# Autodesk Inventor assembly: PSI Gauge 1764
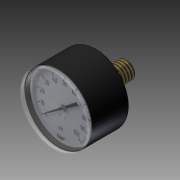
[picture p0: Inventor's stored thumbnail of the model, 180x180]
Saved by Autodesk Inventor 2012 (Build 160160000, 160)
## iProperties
Created: 2010-02
Part Number: PSI Gauge 1764
Document SubType Name: Assembly
Designer: jgehrig
Author: jgehrig
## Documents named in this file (5)
- R:\CAD Archives\Pneumatics_1764\PSI_Gauge_1764\PSI_Gauge_1764.iam
- R:\CAD Archives\Pneumatics_1764\PSI_Gauge_1764\PSI_Gauge_Base_1764.ipt
- R:\CAD Archives\Pneumatics_1764\PSI_Gauge_1764\PSI_Gauge_Screw_1764.ipt
- R:\CAD Archives\Pneumatics_1764\PSI_Gauge_1764\PSI_Gauge_Cap_1764.ipt
- R:\CAD Archives\Pneumatics_1764\PSI_Gauge_1764\PSI_Guage_Face_1764.ipt
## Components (4 placed, 4 different names)
1. PSI_Gauge_Base_1764:1 — Mate:1, Mate:2, Insert:1, Mate:3, Mate:4
2. PSI_Gauge_Screw_1764:1 — Mate:3, Mate:4
3. PSI_Gauge_Cap_1764:1 — Insert:1
4. PSI_Guage_Face_1764:1 — Mate:1, Mate:2
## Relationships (5: Mate 4, Insert 1)
- Mate:1: PSI_Gauge_Base_1764:1 ↔ PSI_Guage_Face_1764:1
- Mate:2: PSI_Gauge_Base_1764:1 ↔ PSI_Guage_Face_1764:1
- Insert:1: PSI_Gauge_Base_1764:1 ↔ PSI_Gauge_Cap_1764:1
- Mate:3: PSI_Gauge_Base_1764:1 ↔ PSI_Gauge_Screw_1764:1
- Mate:4: PSI_Gauge_Base_1764:1 ↔ PSI_Gauge_Screw_1764:1
